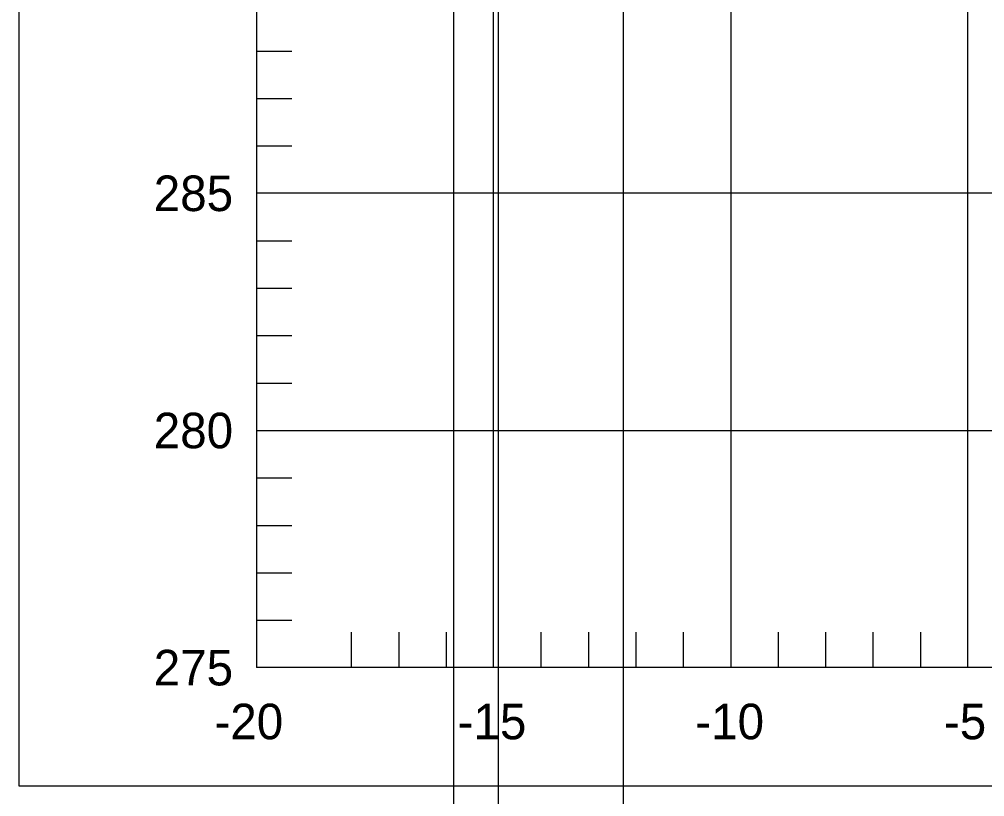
# Model space of a CAD drawing. Extents: x 1578769 to 1579225, y 724002 to 724828.
# Drawn here: x 1578815.03 to 1578835.39, y 724384.43 to 724400.81 of the extents above; entities that cross this region are included whole.
import ezdxf

# ---------------------------------------------------------------- set-up
doc = ezdxf.new("R2010")
doc.units = 0
for name, color, linetype in [('1', 7, 'Continuous'), ('Default', 7, 'Continuous'), ('Old_Level_1', 7, 'Continuous'), ('Old_Level_41', 7, 'Continuous'), ('Old_Level_42', 7, 'Continuous')]:
    doc.layers.add(name, color=color, linetype=linetype)

msp = doc.modelspace()

# ---------------------------------------------------------------- linework, layer by layer
at = {"layer": 'Default'}
for p, q in [((1578824.194, 724303.15), (1578824.194, 724553.15)), ((1578827.766, 724526.976), (1578827.766, 724276.976)), ((1578825.136, 724252.141), (1578825.136, 724502.141))]:
    msp.add_line(p, q, dxfattribs=at)
at = {"layer": 'Old_Level_1'}
msp.add_lwpolyline([(1578815.032, 724419.646), (1578942.532, 724419.646), (1578942.532, 724384.646), (1578815.032, 724384.646)], close=True, dxfattribs=at)
msp.add_lwpolyline([(1578820.032, 724417.146), (1578940.032, 724417.146), (1578940.032, 724387.146), (1578820.032, 724387.146)], dxfattribs=at)
at = {"layer": 'Old_Level_41'}
for p, q in [((1578820.032, 724417.146), (1578820.032, 724387.146)), ((1578825.032, 724387.146), (1578825.032, 724417.146)), ((1578830.032, 724417.146), (1578830.032, 724387.146)), ((1578835.032, 724387.146), (1578835.032, 724417.146))]:
    msp.add_line(p, q, dxfattribs=at)
for points in [[(1578940.032, 724397.146), (1578820.032, 724397.146)], [(1578820.032, 724392.146), (1578940.032, 724392.146)]]:
    msp.add_lwpolyline(points, dxfattribs=at)
at = {"layer": 'Old_Level_42'}
for p, q in [((1578820.032, 724400.146), (1578820.782, 724400.146)), ((1578820.032, 724399.146), (1578820.782, 724399.146)), ((1578820.032, 724398.146), (1578820.782, 724398.146)), ((1578820.032, 724396.146), (1578820.782, 724396.146)), ((1578820.032, 724395.146), (1578820.782, 724395.146)), ((1578820.032, 724394.146), (1578820.782, 724394.146)), ((1578820.032, 724393.146), (1578820.782, 724393.146)), ((1578820.032, 724391.146), (1578820.782, 724391.146)), ((1578820.032, 724390.146), (1578820.782, 724390.146)), ((1578820.032, 724389.146), (1578820.782, 724389.146)), ((1578820.032, 724388.146), (1578820.782, 724388.146)), ((1578822.032, 724387.896), (1578822.032, 724387.146)), ((1578823.032, 724387.896), (1578823.032, 724387.146)), ((1578824.032, 724387.896), (1578824.032, 724387.146)), ((1578826.032, 724387.896), (1578826.032, 724387.146)), ((1578827.032, 724387.896), (1578827.032, 724387.146)), ((1578828.032, 724387.896), (1578828.032, 724387.146)), ((1578829.032, 724387.896), (1578829.032, 724387.146)), ((1578831.032, 724387.896), (1578831.032, 724387.146)), ((1578832.032, 724387.896), (1578832.032, 724387.146)), ((1578833.032, 724387.896), (1578833.032, 724387.146)), ((1578834.032, 724387.896), (1578834.032, 724387.146))]:
    msp.add_line(p, q, dxfattribs=at)

# ---------------------------------------------------------------- texts
at = {"layer": '1'}
for s, p in [('285', (1578817.867, 724396.771)), ('280', (1578817.867, 724391.771)), ('275', (1578817.867, 724386.771)), ('-20', (1578819.147, 724385.636)), ('-15', (1578824.274, 724385.636)), ('-10', (1578829.286, 724385.636)), ('-5', (1578834.528, 724385.636))]:
    msp.add_text(s, height=0.75, dxfattribs=at).set_placement(p)

doc.saveas('drawing.dxf')
